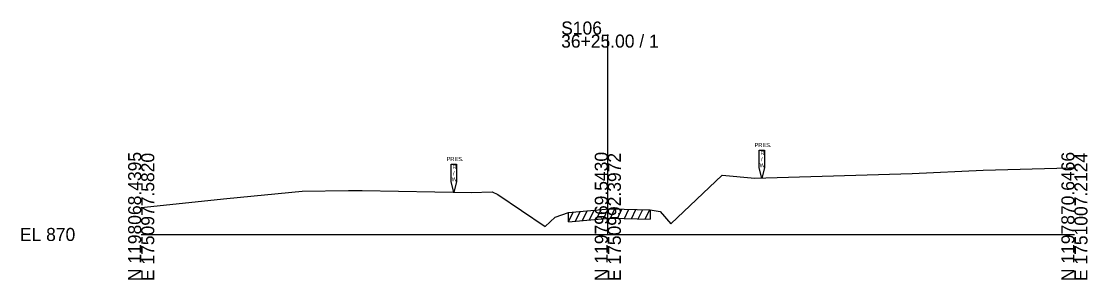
# Model space of a CAD drawing. Extents: x -26 to 1203, y -10 to 19527.
# Drawn here: x 974.3 to 1202.8, y 2490.3 to 2545.7 of the extents above; entities that cross this region are included whole.
import ezdxf

# ---------------------------------------------------------------- set-up
doc = ezdxf.new("R2010")
doc.units = 0
for name, color, linetype in [('RD_GPK_XS_Cell', 7, 'Continuous'), ('RD_XS_ExGround', 7, 'Continuous'), ('RD_XS_ExPaveRet', 7, 'Continuous'), ('RD_XS_ExRW', 7, 'Continuous'), ('RD_XS_TX_Elev_EX', 7, 'Continuous')]:
    doc.layers.add(name, color=color, linetype=linetype)

msp = doc.modelspace()

# ---------------------------------------------------------------- linework, layer by layer
at = {"layer": 'RD_GPK_XS_Cell'}
for p, q in [((1100, 2500), (1100, 2542.84)), ((1000, 2500), (1100, 2500)), ((1100, 2500), (1200, 2500))]:
    msp.add_line(p, q, dxfattribs=at)
at = {"layer": 'RD_XS_ExGround'}
msp.add_lwpolyline([(1000, 2505.79), (1018.36, 2507.71), (1034.5, 2509.31), (1044.4, 2509.41), (1047.34, 2509.44), (1070.72, 2509.02), (1075.24, 2509.11), (1076.41, 2508.56), (1086.57, 2501.72), (1088.74, 2503.69), (1091.54, 2504.72), (1100.29, 2505.49), (1100.75, 2505.48), (1109.1, 2505.3), (1111.2, 2504.93), (1113.48, 2502.25), (1124.5, 2512.71), (1131.48, 2512.04), (1133.87, 2512.1), (1165.22, 2513.04), (1180.43, 2513.76), (1198.88, 2514.28), (1200, 2514.26)], dxfattribs=at)
at = {"layer": 'RD_XS_ExPaveRet'}
for p, q in [((1091.54, 2502.72), (1092.59, 2504.81)), ((1091.54, 2502.72), (1091.54, 2504.72)), ((1093.04, 2502.85), (1094.09, 2504.94)), ((1094.54, 2502.98), (1095.59, 2505.08)), ((1096.04, 2503.12), (1097.09, 2505.21)), ((1097.54, 2503.25), (1098.59, 2505.34)), ((1099.04, 2503.38), (1100.09, 2505.47)), ((1100.54, 2503.48), (1101.53, 2505.46)), ((1102.04, 2503.45), (1103.03, 2505.43)), ((1103.54, 2503.42), (1104.53, 2505.4)), ((1105.04, 2503.38), (1106.03, 2505.36)), ((1106.54, 2503.35), (1107.53, 2505.33)), ((1108.04, 2503.32), (1109.03, 2505.3)), ((1109.1, 2505.3), (1109.1, 2503.3)), ((1091.54, 2502.72), (1100.29, 2503.49)), ((1100.29, 2503.49), (1100.75, 2503.48)), ((1100.75, 2503.48), (1109.1, 2503.3))]:
    msp.add_line(p, q, dxfattribs=at)
at = {"layer": 'RD_XS_ExRW'}
for points in [[(1132.45, 2518.09), (1133.55, 2518.09), (1133.55, 2514.27), (1133, 2512.08), (1132.45, 2514.27)], [(1066.45, 2515.1), (1067.55, 2515.1), (1067.55, 2511.28), (1067, 2509.09), (1066.45, 2511.28)]]:
    msp.add_lwpolyline(points, close=True, dxfattribs=at)

# ---------------------------------------------------------------- texts
at = {"layer": 'RD_GPK_XS_Cell'}
for s, p in [('S106', (1090, 2542.84)), ('36+25.00 / 1', (1090, 2540.04)), ('EL 870', (974, 2498.6))]:
    msp.add_text(s, height=2.8, dxfattribs=at).set_placement(p)
for s, p in [('N 1198068.4395', (1000, 2490)), ('E 1750977.5820', (1002.8, 2490)), ('N 1197969.5430', (1100, 2490)), ('E 1750992.3972', (1102.8, 2490)), ('N 1197870.6466', (1200, 2490)), ('E 1751007.2124', (1202.8, 2490))]:
    msp.add_text(s, height=2.8, rotation=90, dxfattribs=at).set_placement(p)
at = {"layer": 'RD_XS_ExRW'}
for s, p in [('PRES.', (1131.45, 2518.72)), ('PRES.', (1065.45, 2515.73)), ('R', (1132.71, 2517)), ('/', (1132.83, 2515.69)), ('R', (1066.71, 2514.01)), ('W', (1132.53, 2514.38)), ('W', (1066.53, 2511.39)), ('/', (1066.83, 2512.7))]:
    msp.add_text(s, height=0.875, dxfattribs=at).set_placement(p)
at = {"layer": 'RD_XS_TX_Elev_EX'}
msp.add_text('872.73', height=0.0975, rotation=90, dxfattribs=at).set_placement((1100.1, 2505.46))

doc.saveas('drawing.dxf')
